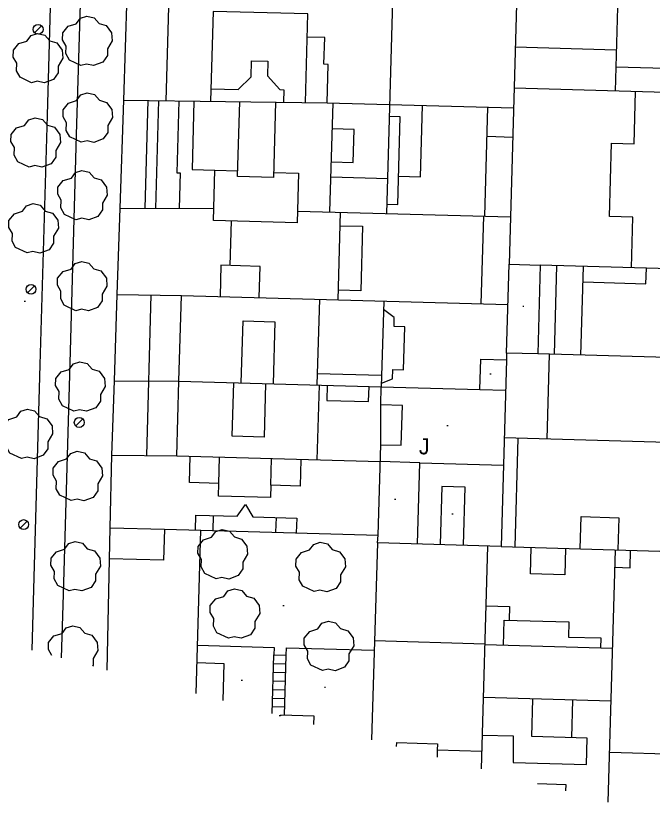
# Model space of a CAD drawing. Extents: x 431390 to 432653, y 4586754 to 4589600.
# Drawn here: x 431475.8 to 431527.3, y 4586864.4 to 4586927.9 of the extents above; entities that cross this region are included whole.
import ezdxf

# ---------------------------------------------------------------- set-up
doc = ezdxf.new("R2010")
doc.units = 0
for name, color, linetype in [('COM_03LS_LN', 7, 'Continuous'), ('CON_01_LN', 7, 'Continuous'), ('CON_01FI_LN', 7, 'Continuous'), ('CON_03_LN', 7, 'Continuous'), ('CON_04_LN', 7, 'Continuous'), ('CON_07_LN', 7, 'Continuous'), ('CON_16_LN', 7, 'Continuous'), ('CON_23_LN', 7, 'Continuous'), ('CON_29_LN', 7, 'Continuous'), ('ENE_06_PT', 7, 'Continuous'), ('ORO_03_PT', 7, 'Continuous'), ('TOP_15JA_TX', 7, 'Continuous'), ('VEG_03_PT', 7, 'Continuous')]:
    doc.layers.add(name, color=color, linetype=linetype)

msp = doc.modelspace()

# ---------------------------------------------------------------- linework, layer by layer
at = {"layer": 'COM_03LS_LN'}
for points in [[(431469.696, 4586975.695), (431476.906, 4586975.488), (431479.854, 4586973.234), (431479.601, 4586964.134), (431479.207, 4586950.883), (431478.706, 4586933.535), (431478.322, 4586919.868), (431477.743, 4586899.735), (431477.22, 4586881.582), (431477.085, 4586876.66)], [(431492.109, 4586975.056), (431485.307, 4586975.242), (431482.253, 4586973.182), (431481.949, 4586962.338), (431481.611, 4586950.929), (431481.225, 4586936.834), (431480.67, 4586918.321), (431480.161, 4586899.864), (431479.606, 4586881.161), (431479.462, 4586876.033)]]:
    msp.add_lwpolyline(points, dxfattribs=at)
at = {"layer": 'CON_01_LN'}
msp.add_lwpolyline([(431483.175, 4586875.055), (431483.419, 4586886.556), (431483.555, 4586892.411), (431483.774, 4586898.42), (431483.985, 4586905.404), (431484.232, 4586912.384), (431484.515, 4586921.118), (431484.791, 4586929.649), (431484.974, 4586936.665), (431485.208, 4586943.703), (431485.38, 4586950.747), (431485.585, 4586957.722), (431486.032, 4586972.689), (431492.071, 4586972.503)], dxfattribs=at)
at = {"layer": 'CON_01FI_LN'}
for points in [[(431515.476, 4586900.677), (431515.678, 4586907.848)], [(431515.678, 4586907.848), (431518.198, 4586907.778)], [(431518.198, 4586907.778), (431517.999, 4586900.606)], [(431490.738, 4586886.361), (431505.097, 4586885.955), (431505.304, 4586893.266), (431506.96, 4586893.219), (431507.051, 4586896.431), (431505.303, 4586896.48), (431505.344, 4586897.948), (431513.313, 4586897.723), (431513.383, 4586900.186), (431515.461, 4586900.127)], [(431515.461, 4586900.127), (431515.035, 4586885.047)], [(431517.999, 4586900.606), (431515.476, 4586900.677)], [(431490.365, 4586873.159), (431490.738, 4586886.361)], [(431515.035, 4586885.047), (431505.03, 4586885.342), (431504.56, 4586869.417)], [(431499.887, 4586870.649), (431499.906, 4586871.327), (431497.197, 4586871.403), (431497.196, 4586871.358)]]:
    msp.add_lwpolyline(points, dxfattribs=at)
at = {"layer": 'CON_03_LN'}
for points in [[(431516.271, 4586928.849), (431515.678, 4586907.848)], [(431547.243, 4586921.202), (431516.08, 4586922.078)], [(431484.515, 4586921.118), (431500.971, 4586920.906), (431516.035, 4586920.487)], [(431484.232, 4586912.384), (431491.798, 4586912.347)], [(431498.573, 4586912.157), (431515.786, 4586911.674)], [(431546.842, 4586906.981), (431518.198, 4586907.778)], [(431483.985, 4586905.404), (431489.175, 4586905.34), (431515.586, 4586904.594)], [(431515.476, 4586900.677), (431515.461, 4586900.127)], [(431546.639, 4586899.798), (431517.999, 4586900.606)], [(431483.774, 4586898.42), (431488.979, 4586898.411), (431505.344, 4586897.948)], [(431546.445, 4586892.945), (431515.283, 4586893.824)], [(431483.555, 4586892.411), (431488.808, 4586892.367), (431505.265, 4586891.902)], [(431483.419, 4586886.556), (431487.811, 4586886.443), (431490.738, 4586886.361)], [(431513.433, 4586867.078), (431513.956, 4586885.079)], [(431515.035, 4586885.047), (431546.197, 4586884.127)], [(431523.7, 4586864.372), (431524.276, 4586884.774)]]:
    msp.add_lwpolyline(points, dxfattribs=at)
at = {"layer": 'CON_04_LN'}
for points in [[(431488.158, 4586929.62), (431487.918, 4586921.074)], [(431505.801, 4586911.954), (431506.283, 4586929.131)], [(431499.214, 4586920.928), (431499.413, 4586928.08), (431491.74, 4586928.293), (431491.538, 4586921.028)], [(431524.433, 4586928.619), (431524.242, 4586921.849)], [(431500.971, 4586920.906), (431501.057, 4586924.007), (431500.707, 4586924.017), (431500.767, 4586926.176), (431499.361, 4586926.215)], [(431491.566, 4586922.04), (431493.76, 4586921.979), (431494.808, 4586922.989), (431494.844, 4586924.296), (431496.18, 4586924.259), (431496.147, 4586923.076), (431497.131, 4586921.972), (431497.464, 4586921.963), (431497.436, 4586920.951)], [(431524.297, 4586923.816), (431529.305, 4586923.674), (431529.249, 4586921.708)], [(431525.573, 4586907.573), (431525.687, 4586911.656), (431523.791, 4586911.709), (431523.956, 4586917.63), (431525.784, 4586917.579), (431525.901, 4586921.802)], [(431486.459, 4586921.093), (431486.217, 4586912.374)], [(431487.329, 4586921.082), (431487.088, 4586912.37)], [(431488.981, 4586921.061), (431488.82, 4586915.251), (431489.079, 4586915.244), (431488.999, 4586912.361)], [(431490.196, 4586921.045), (431490.042, 4586915.505), (431491.885, 4586915.454)], [(431496.785, 4586920.96), (431496.616, 4586914.861), (431493.728, 4586914.941), (431493.896, 4586920.997)], [(431501.193, 4586912.083), (431501.44, 4586920.893)], [(431506.733, 4586914.979), (431508.503, 4586914.93), (431508.664, 4586920.692)], [(431513.711, 4586911.732), (431513.958, 4586920.545)], [(431505.822, 4586912.704), (431506.669, 4586912.68), (431506.867, 4586919.77), (431506.021, 4586919.794)], [(431501.306, 4586916.12), (431503.08, 4586916.07), (431503.155, 4586918.746), (431501.381, 4586918.796)], [(431513.892, 4586918.195), (431515.969, 4586918.137)], [(431496.627, 4586915.273), (431498.659, 4586915.216), (431498.546, 4586911.207), (431491.771, 4586911.398), (431491.885, 4586915.454), (431493.741, 4586915.402)], [(431501.272, 4586914.907), (431505.88, 4586914.778)], [(431501.857, 4586904.982), (431502.057, 4586912.059)], [(431513.426, 4586904.655), (431513.626, 4586911.735)], [(431502.026, 4586910.972), (431503.832, 4586910.921), (431503.685, 4586905.712), (431501.879, 4586905.763)], [(431495.481, 4586905.162), (431495.552, 4586907.684), (431492.373, 4586907.774), (431492.302, 4586905.252)], [(431519.515, 4586907.741), (431519.315, 4586900.569)], [(431521.489, 4586900.508), (431521.691, 4586907.681)], [(431521.656, 4586906.422), (431526.742, 4586906.279), (431526.777, 4586907.539)], [(431486.378, 4586892.387), (431486.745, 4586905.37)], [(431488.808, 4586892.367), (431488.979, 4586898.411), (431489.175, 4586905.34)], [(431500.34, 4586905.025), (431500.144, 4586898.095)], [(431505.54, 4586904.878), (431505.344, 4586897.948)], [(431505.352, 4586898.231), (431506.26, 4586898.6), (431506.281, 4586899.34), (431507.136, 4586899.316), (431507.235, 4586902.8), (431506.373, 4586902.824), (431506.394, 4586903.559), (431505.52, 4586904.184)], [(431494.025, 4586898.268), (431494.167, 4586903.276), (431496.732, 4586903.203), (431496.59, 4586898.196)], [(431518.919, 4586900.58), (431518.727, 4586893.727)], [(431500.171, 4586899.035), (431505.371, 4586898.887)], [(431495.982, 4586898.213), (431495.86, 4586893.889), (431493.288, 4586893.962), (431493.41, 4586898.286)], [(431500.169, 4586892.046), (431500.34, 4586898.09)], [(431500.961, 4586898.072), (431500.927, 4586896.853), (431504.317, 4586896.757), (431504.351, 4586897.976)], [(431505.304, 4586893.266), (431505.303, 4586896.48)], [(431516.379, 4586893.793), (431516.133, 4586885.015)], [(431498.834, 4586892.084), (431498.773, 4586889.929), (431496.401, 4586889.996), (431496.373, 4586889), (431492.175, 4586889.119), (431492.204, 4586890.14), (431489.821, 4586890.207), (431489.881, 4586892.337)], [(431492.204, 4586890.14), (431492.264, 4586892.269)], [(431496.401, 4586889.996), (431496.462, 4586892.151)], [(431490.31, 4586886.373), (431490.344, 4586887.578), (431493.691, 4586887.482), (431494.37, 4586888.43), (431494.95, 4586887.446), (431498.502, 4586887.345), (431498.468, 4586886.142)], [(431491.742, 4586887.538), (431491.708, 4586886.334)], [(431521.421, 4586884.858), (431521.498, 4586887.462), (431524.543, 4586887.372), (431524.466, 4586884.769)], [(431496.835, 4586887.392), (431496.801, 4586886.19)], [(431487.811, 4586886.443), (431487.74, 4586883.929), (431483.366, 4586884.053)], [(431520.241, 4586884.893), (431520.177, 4586882.74), (431517.407, 4586882.822), (431517.471, 4586884.975)], [(431524.236, 4586883.363), (431525.458, 4586883.328), (431525.498, 4586884.738)], [(431513.815, 4586880.237), (431515.711, 4586880.182), (431515.679, 4586879.09)], [(431515.226, 4586877.054), (431515.284, 4586879.101), (431520.521, 4586878.953), (431520.486, 4586877.725), (431523.096, 4586877.651), (431523.073, 4586876.832)], [(431504.797, 4586877.444), (431513.726, 4586877.181)], [(431524.051, 4586876.804), (431513.724, 4586877.096)], [(431523.93, 4586872.537), (431513.6, 4586872.829)], [(431513.512, 4586869.803), (431516.01, 4586869.73), (431516, 4586867.584), (431521.925, 4586867.412), (431521.987, 4586869.557), (431517.508, 4586869.687), (431517.596, 4586872.716)], [(431520.801, 4586872.625), (431520.715, 4586869.594)], [(431506.582, 4586868.884), (431506.591, 4586869.202), (431509.884, 4586869.107), (431509.869, 4586868.574)], [(431513.473, 4586868.469), (431509.869, 4586868.574), (431509.853, 4586868.022)], [(431523.814, 4586868.412), (431529.293, 4586868.257)], [(431517.964, 4586865.884), (431520.257, 4586865.817), (431520.241, 4586865.283)]]:
    msp.add_lwpolyline(points, dxfattribs=at)
at = {"layer": 'CON_07_LN'}
for points in [[(431508.274, 4586885.246), (431508.468, 4586891.813), (431515.221, 4586891.614)], [(431511.996, 4586885.137), (431512.135, 4586889.832), (431510.25, 4586889.888), (431510.111, 4586885.192)], [(431490.436, 4586875.655), (431492.615, 4586875.594), (431492.531, 4586872.588)]]:
    msp.add_lwpolyline(points, dxfattribs=at)
at = {"layer": 'CON_16_LN'}
for points in [[(431513.313, 4586897.723), (431515.391, 4586897.664)], [(431508.468, 4586891.813), (431505.265, 4586891.902)], [(431505.03, 4586885.342), (431505.097, 4586885.955)], [(431490.475, 4586877.056), (431496.68, 4586876.881), (431496.663, 4586876.276)], [(431497.663, 4586876.248), (431497.68, 4586876.853), (431504.774, 4586876.655)]]:
    msp.add_lwpolyline(points, dxfattribs=at)
at = {"layer": 'CON_23_LN'}
for points in [[(431496.528, 4586871.534), (431496.663, 4586876.276)], [(431496.663, 4586876.276), (431497.663, 4586876.248)], [(431497.525, 4586871.394), (431497.663, 4586876.248)], [(431496.643, 4586875.58), (431497.643, 4586875.552)], [(431496.623, 4586874.884), (431497.623, 4586874.856)], [(431496.604, 4586874.188), (431497.604, 4586874.16)], [(431496.584, 4586873.492), (431497.584, 4586873.464)], [(431496.564, 4586872.796), (431497.564, 4586872.768)], [(431496.544, 4586872.1), (431497.544, 4586872.072)], [(431497.083, 4586871.388), (431497.196, 4586871.385)]]:
    msp.add_lwpolyline(points, dxfattribs=at)
at = {"layer": 'CON_29_LN'}
for points in [[(431516.174, 4586925.424), (431524.336, 4586925.193)], [(431493.202, 4586911.358), (431493.101, 4586907.753)]]:
    msp.add_lwpolyline(points, dxfattribs=at)
at = {"layer": 'ENE_06_PT'}
for p, q in [((431477.88, 4586927.122), (431477.314, 4586926.556)), ((431477.301, 4586906.111), (431476.735, 4586905.545)), ((431481.202, 4586895.35), (431480.636, 4586894.784)), ((431476.707, 4586887.098), (431476.141, 4586886.532))]:
    msp.add_line(p, q, dxfattribs=at)
for centre in [(431477.597, 4586926.839), (431477.018, 4586905.828), (431480.919, 4586895.067), (431476.424, 4586886.815)]:
    msp.add_circle(centre, 0.4, dxfattribs=at)
at = {"layer": 'ORO_03_PT'}
for p, q in [((431476.464, 4586904.874), (431476.564, 4586904.874)), ((431516.78, 4586904.46), (431516.88, 4586904.46)), ((431514.13, 4586899), (431514.23, 4586899)), ((431510.64, 4586894.81), (431510.74, 4586894.81)), ((431506.41, 4586888.88), (431506.51, 4586888.88)), ((431511.06, 4586887.69), (431511.16, 4586887.69)), ((431497.38, 4586880.28), (431497.48, 4586880.28)), ((431494.02, 4586874.23), (431494.12, 4586874.23)), ((431500.74, 4586873.67), (431500.84, 4586873.67))]:
    msp.add_line(p, q, dxfattribs=at)
at = {"layer": 'VEG_03_PT'}
for points in [[(431481.049, 4586923.922), (431480.122, 4586924.357), (431479.834, 4586924.878), (431479.857, 4586925.492), (431479.575, 4586925.984), (431479.583, 4586926.547), (431480.024, 4586927.082), (431480.677, 4586927.286), (431481.012, 4586927.737), (431481.538, 4586927.907), (431482.118, 4586927.774), (431482.518, 4586927.308), (431483.092, 4586927.138), (431483.526, 4586926.555), (431483.575, 4586925.913), (431483.192, 4586925.266), (431483.192, 4586924.716), (431482.82, 4586924.182), (431482.081, 4586923.907), (431481.516, 4586924.035), (431481.049, 4586923.922)], [(431477.063, 4586922.527), (431476.136, 4586922.962), (431475.848, 4586923.483), (431475.871, 4586924.097), (431475.589, 4586924.589), (431475.597, 4586925.152), (431476.038, 4586925.687), (431476.691, 4586925.891), (431477.026, 4586926.342), (431477.552, 4586926.512), (431478.132, 4586926.379), (431478.532, 4586925.913), (431479.106, 4586925.743), (431479.54, 4586925.16), (431479.589, 4586924.518), (431479.206, 4586923.871), (431479.206, 4586923.321), (431478.834, 4586922.787), (431478.095, 4586922.512), (431477.53, 4586922.64), (431477.063, 4586922.527)], [(431481.08, 4586917.719), (431480.153, 4586918.154), (431479.865, 4586918.675), (431479.888, 4586919.289), (431479.606, 4586919.781), (431479.614, 4586920.344), (431480.055, 4586920.879), (431480.708, 4586921.083), (431481.043, 4586921.534), (431481.569, 4586921.704), (431482.149, 4586921.571), (431482.549, 4586921.105), (431483.123, 4586920.935), (431483.557, 4586920.352), (431483.606, 4586919.71), (431483.223, 4586919.063), (431483.223, 4586918.513), (431482.851, 4586917.979), (431482.112, 4586917.704), (431481.547, 4586917.832), (431481.08, 4586917.719)], [(431476.872, 4586915.709), (431475.945, 4586916.144), (431475.657, 4586916.665), (431475.68, 4586917.279), (431475.398, 4586917.771), (431475.406, 4586918.334), (431475.847, 4586918.869), (431476.5, 4586919.073), (431476.835, 4586919.524), (431477.361, 4586919.694), (431477.941, 4586919.561), (431478.341, 4586919.095), (431478.915, 4586918.925), (431479.349, 4586918.342), (431479.398, 4586917.7), (431479.015, 4586917.053), (431479.015, 4586916.503), (431478.643, 4586915.969), (431477.904, 4586915.694), (431477.339, 4586915.822), (431476.872, 4586915.709)], [(431480.652, 4586911.452), (431479.725, 4586911.887), (431479.437, 4586912.408), (431479.46, 4586913.022), (431479.178, 4586913.514), (431479.186, 4586914.077), (431479.627, 4586914.612), (431480.28, 4586914.816), (431480.615, 4586915.267), (431481.141, 4586915.437), (431481.721, 4586915.304), (431482.121, 4586914.838), (431482.695, 4586914.668), (431483.129, 4586914.085), (431483.178, 4586913.443), (431482.795, 4586912.796), (431482.795, 4586912.246), (431482.423, 4586911.712), (431481.684, 4586911.437), (431481.119, 4586911.565), (431480.652, 4586911.452)], [(431476.703, 4586908.771), (431475.776, 4586909.206), (431475.488, 4586909.727), (431475.511, 4586910.341), (431475.229, 4586910.833), (431475.237, 4586911.396), (431475.678, 4586911.931), (431476.331, 4586912.135), (431476.666, 4586912.586), (431477.192, 4586912.756), (431477.772, 4586912.623), (431478.172, 4586912.157), (431478.746, 4586911.987), (431479.18, 4586911.404), (431479.229, 4586910.762), (431478.846, 4586910.115), (431478.846, 4586909.565), (431478.474, 4586909.031), (431477.735, 4586908.756), (431477.17, 4586908.884), (431476.703, 4586908.771)], [(431480.633, 4586904.101), (431479.706, 4586904.536), (431479.418, 4586905.057), (431479.441, 4586905.671), (431479.159, 4586906.163), (431479.167, 4586906.726), (431479.608, 4586907.261), (431480.261, 4586907.465), (431480.596, 4586907.916), (431481.122, 4586908.086), (431481.702, 4586907.953), (431482.102, 4586907.487), (431482.676, 4586907.317), (431483.11, 4586906.734), (431483.159, 4586906.092), (431482.776, 4586905.445), (431482.776, 4586904.895), (431482.404, 4586904.361), (431481.665, 4586904.086), (431481.1, 4586904.214), (431480.633, 4586904.101)], [(431480.484, 4586895.987), (431479.557, 4586896.422), (431479.269, 4586896.943), (431479.292, 4586897.557), (431479.01, 4586898.049), (431479.018, 4586898.612), (431479.459, 4586899.147), (431480.112, 4586899.351), (431480.447, 4586899.802), (431480.973, 4586899.972), (431481.553, 4586899.839), (431481.953, 4586899.373), (431482.527, 4586899.203), (431482.961, 4586898.62), (431483.01, 4586897.978), (431482.627, 4586897.331), (431482.627, 4586896.781), (431482.255, 4586896.247), (431481.516, 4586895.972), (431480.951, 4586896.1), (431480.484, 4586895.987)], [(431476.243, 4586892.153), (431475.316, 4586892.588), (431475.028, 4586893.109), (431475.051, 4586893.723), (431474.769, 4586894.215), (431474.777, 4586894.778), (431475.218, 4586895.313), (431475.871, 4586895.517), (431476.206, 4586895.968), (431476.732, 4586896.138), (431477.312, 4586896.005), (431477.712, 4586895.539), (431478.286, 4586895.369), (431478.72, 4586894.786), (431478.769, 4586894.144), (431478.386, 4586893.497), (431478.386, 4586892.947), (431478.014, 4586892.413), (431477.275, 4586892.138), (431476.71, 4586892.266), (431476.243, 4586892.153)], [(431480.271, 4586888.751), (431479.344, 4586889.186), (431479.056, 4586889.707), (431479.079, 4586890.321), (431478.797, 4586890.813), (431478.805, 4586891.376), (431479.246, 4586891.911), (431479.899, 4586892.115), (431480.234, 4586892.566), (431480.76, 4586892.736), (431481.34, 4586892.603), (431481.74, 4586892.137), (431482.314, 4586891.967), (431482.748, 4586891.384), (431482.797, 4586890.742), (431482.414, 4586890.095), (431482.414, 4586889.545), (431482.042, 4586889.011), (431481.303, 4586888.736), (431480.738, 4586888.864), (431480.271, 4586888.751)], [(431491.994, 4586882.431), (431491.067, 4586882.866), (431490.779, 4586883.387), (431490.802, 4586884.001), (431490.52, 4586884.493), (431490.528, 4586885.056), (431490.969, 4586885.591), (431491.622, 4586885.795), (431491.957, 4586886.246), (431492.483, 4586886.416), (431493.063, 4586886.283), (431493.463, 4586885.817), (431494.037, 4586885.647), (431494.471, 4586885.064), (431494.52, 4586884.422), (431494.137, 4586883.775), (431494.137, 4586883.225), (431493.765, 4586882.691), (431493.026, 4586882.416), (431492.461, 4586882.544), (431491.994, 4586882.431)], [(431480.103, 4586881.465), (431479.176, 4586881.9), (431478.888, 4586882.421), (431478.911, 4586883.035), (431478.629, 4586883.527), (431478.637, 4586884.09), (431479.078, 4586884.625), (431479.731, 4586884.829), (431480.066, 4586885.28), (431480.592, 4586885.45), (431481.172, 4586885.317), (431481.572, 4586884.851), (431482.146, 4586884.681), (431482.58, 4586884.098), (431482.629, 4586883.456), (431482.246, 4586882.809), (431482.246, 4586882.259), (431481.874, 4586881.725), (431481.135, 4586881.45), (431480.57, 4586881.578), (431480.103, 4586881.465)], [(431499.914, 4586881.401), (431498.987, 4586881.836), (431498.699, 4586882.357), (431498.722, 4586882.971), (431498.44, 4586883.463), (431498.448, 4586884.026), (431498.889, 4586884.561), (431499.542, 4586884.765), (431499.877, 4586885.216), (431500.403, 4586885.386), (431500.983, 4586885.253), (431501.383, 4586884.787), (431501.957, 4586884.617), (431502.391, 4586884.034), (431502.44, 4586883.392), (431502.057, 4586882.745), (431502.057, 4586882.195), (431501.685, 4586881.661), (431500.946, 4586881.386), (431500.381, 4586881.514), (431499.914, 4586881.401)], [(431492.984, 4586877.641), (431492.057, 4586878.076), (431491.769, 4586878.597), (431491.792, 4586879.211), (431491.51, 4586879.703), (431491.518, 4586880.266), (431491.959, 4586880.801), (431492.612, 4586881.005), (431492.947, 4586881.456), (431493.473, 4586881.626), (431494.053, 4586881.493), (431494.453, 4586881.027), (431495.027, 4586880.857), (431495.461, 4586880.274), (431495.51, 4586879.632), (431495.127, 4586878.985), (431495.127, 4586878.435), (431494.755, 4586877.901), (431494.016, 4586877.626), (431493.451, 4586877.754), (431492.984, 4586877.641)], [(431478.704, 4586876.233), (431478.427, 4586876.717), (431478.435, 4586877.28), (431478.876, 4586877.815), (431479.529, 4586878.019), (431479.864, 4586878.47), (431480.39, 4586878.64), (431480.97, 4586878.507), (431481.37, 4586878.041), (431481.944, 4586877.871), (431482.378, 4586877.288), (431482.427, 4586876.646), (431482.044, 4586875.999), (431482.044, 4586875.449), (431481.987, 4586875.368)], [(431500.584, 4586875.021), (431499.657, 4586875.456), (431499.369, 4586875.977), (431499.392, 4586876.591), (431499.11, 4586877.083), (431499.118, 4586877.646), (431499.559, 4586878.181), (431500.212, 4586878.385), (431500.547, 4586878.836), (431501.073, 4586879.006), (431501.653, 4586878.873), (431502.053, 4586878.407), (431502.627, 4586878.237), (431503.061, 4586877.654), (431503.11, 4586877.012), (431502.727, 4586876.365), (431502.727, 4586875.815), (431502.355, 4586875.281), (431501.616, 4586875.006), (431501.051, 4586875.134), (431500.584, 4586875.021)]]:
    msp.add_lwpolyline(points, dxfattribs=at)

# ---------------------------------------------------------------- texts
at = {"layer": 'TOP_15JA_TX'}
msp.add_text('J', height=1.3, dxfattribs=at).set_placement((431508.379, 4586892.488))

doc.saveas('drawing.dxf')
